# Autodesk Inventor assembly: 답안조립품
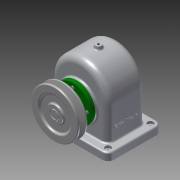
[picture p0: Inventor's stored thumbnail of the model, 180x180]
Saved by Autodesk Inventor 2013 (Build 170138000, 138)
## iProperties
Created: 2016-10
Part Number: 답안조립품
Document SubType Name: Assembly
Designer: cad10
Author: cad10
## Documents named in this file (13)
- C:\Documents and Settings\cad10\바탕 화면\461008V1001\답안조립품.iam
- C:\Documents and Settings\cad10\바탕 화면\461008V1001\부품1.ipt
- C:\Documents and Settings\cad10\바탕 화면\461008V1001\축.ipt
- C:\Documents and Settings\cad10\바탕 화면\461008V1001\키 - 6 x 6 x 22.ipt
- C:\Documents and Settings\cad10\바탕 화면\461008V1001\베어링 6203.ipt
- C:\Documents and Settings\cad10\바탕 화면\461008V1001\부시.ipt
- C:\Documents and Settings\cad10\바탕 화면\461008V1001\오일씰 28 40 8.ipt
- C:\Documents and Settings\cad10\바탕 화면\461008V1001\멈춤나사 - M4x10.ipt
- C:\Documents and Settings\cad10\바탕 화면\461008V1001\V-벨트풀리.ipt
- C:\Documents and Settings\cad10\바탕 화면\461008V1001\앞커버.ipt
- C:\Documents and Settings\cad10\바탕 화면\461008V1001\뒤커버.ipt
- C:\Documents and Settings\cad10\바탕 화면\461008V1001\볼트 M3 x 8.ipt
- C:\Documents and Settings\cad10\바탕 화면\461008V1001\볼트 M3 x 10.ipt
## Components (9 placed, 3 different names)
1. V-벨트풀리:2 — 각도:2
2. ISO 4762 M3 x 8:1
3. ISO 4762 M3 x 8:2
4. ISO 4762 M3 x 8:3
5. ISO 4762 M3 x 8:4
6. ISO 4762 M3 x 10:1
7. ISO 4762 M3 x 10:2
8. ISO 4762 M3 x 10:3
9. ISO 4762 M3 x 10:4
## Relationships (1: Angle 1)
- 각도:2 [Angle]: V-벨트풀리:2
